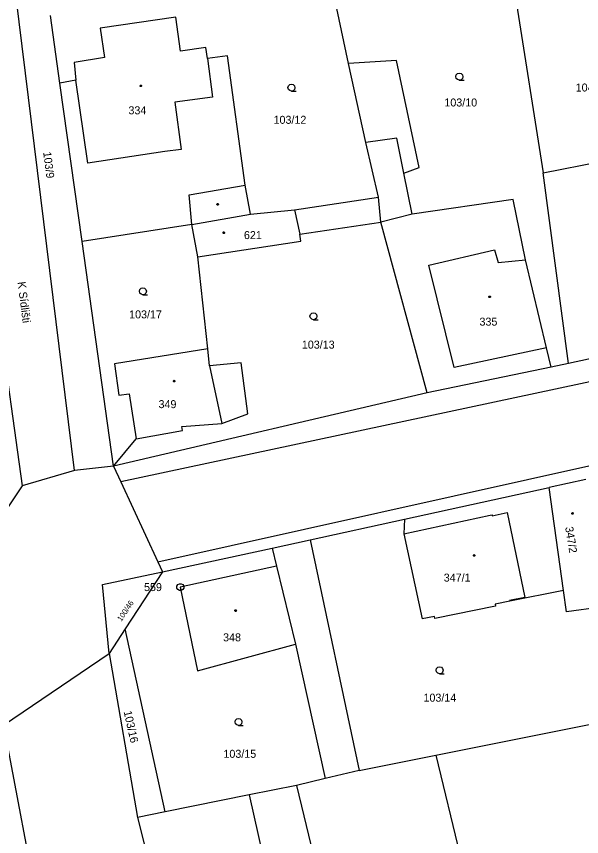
# Model space of a CAD drawing. Extents: x -757994 to -755874, y -1047691 to -1046119.
# Drawn here: x -756803.8 to -756743.8, y -1047170.3 to -1047083.2 of the extents above; entities that cross this region are included whole.
import ezdxf

# ---------------------------------------------------------------- set-up
doc = ezdxf.new("R2010")
doc.units = 0
doc.layers.add('katastrální mapa', color=7, linetype='Continuous')

msp = doc.modelspace()

# ---------------------------------------------------------------- linework, layer by layer
at = {"layer": 'katastrální mapa'}
for p, q in [((-756797.61, -1047131.45), (-756806.3, -1047061.1)), ((-756768.53, -1047088.21), (-756770.54, -1047078.93)), ((-756751.14, -1047079.14), (-756747.9, -1047099.85)), ((-756799.16, -1047090.3), (-756800.17, -1047083.12)), ((-756786.86, -1047083.32), (-756794.88, -1047084.47)), ((-756786.37, -1047086.91), (-756786.86, -1047083.32)), ((-756794.88, -1047084.47), (-756794.45, -1047087.6)), ((-756783.68, -1047086.54), (-756786.37, -1047086.91)), ((-756783.52, -1047087.68), (-756783.68, -1047086.54)), ((-756781.38, -1047087.4), (-756783.52, -1047087.68)), ((-756779.52, -1047101.14), (-756781.38, -1047087.4)), ((-756794.45, -1047087.6), (-756797.65, -1047088.11)), ((-756797.65, -1047088.11), (-756797.48, -1047090)), ((-756783.52, -1047087.68), (-756782.96, -1047091.8)), ((-756763.46, -1047087.89), (-756768.53, -1047088.21)), ((-756766.71, -1047096.61), (-756768.53, -1047088.21)), ((-756761.05, -1047099.28), (-756763.46, -1047087.89)), ((-756797.48, -1047090), (-756799.16, -1047090.3)), ((-756796.2, -1047098.8), (-756797.48, -1047090)), ((-756796.81, -1047107.13), (-756799.16, -1047090.3)), ((-756782.96, -1047091.8), (-756786.98, -1047092.34)), ((-756786.98, -1047092.34), (-756786.3, -1047097.34)), ((-756763.41, -1047096.14), (-756766.71, -1047096.61)), ((-756765.38, -1047102.41), (-756766.71, -1047096.61)), ((-756762.66, -1047099.87), (-756763.41, -1047096.14)), ((-756788.03, -1047097.58), (-756796.2, -1047098.8)), ((-756786.3, -1047097.34), (-756788.03, -1047097.58)), ((-756747.9, -1047099.85), (-756741.46, -1047098.58)), ((-756762.66, -1047099.87), (-756761.05, -1047099.28)), ((-756761.79, -1047104.23), (-756762.66, -1047099.87)), ((-756745.21, -1047120.09), (-756747.9, -1047099.85)), ((-756785.46, -1047102.16), (-756779.52, -1047101.14)), ((-756778.96, -1047104.24), (-756779.52, -1047101.14)), ((-756785.16, -1047105.31), (-756785.46, -1047102.16)), ((-756774.27, -1047103.76), (-756765.38, -1047102.41)), ((-756765.1, -1047105.06), (-756765.38, -1047102.41)), ((-756751.06, -1047102.68), (-756761.79, -1047104.23)), ((-756749.75, -1047109.07), (-756751.06, -1047102.68)), ((-756778.96, -1047104.24), (-756774.27, -1047103.76)), ((-756774.27, -1047103.76), (-756773.7, -1047106.34)), ((-756785.16, -1047105.31), (-756778.96, -1047104.24)), ((-756761.79, -1047104.23), (-756765.1, -1047105.06)), ((-756785.16, -1047105.31), (-756796.81, -1047107.13)), ((-756665.81, -1047105.58), (-756792.7, -1047132.63)), ((-756784.53, -1047108.76), (-756785.16, -1047105.31)), ((-756773.7, -1047106.34), (-756765.1, -1047105.06)), ((-756760.19, -1047123.2), (-756765.1, -1047105.06)), ((-756773.6, -1047107.1), (-756773.7, -1047106.34)), ((-756793.47, -1047130.97), (-756796.81, -1047107.13)), ((-756784.53, -1047108.76), (-756773.6, -1047107.1)), ((-756760.02, -1047109.63), (-756753.05, -1047108.02)), ((-756753.05, -1047108.02), (-756752.68, -1047109.35)), ((-756783.48, -1047118.51), (-756784.53, -1047108.76)), ((-756752.68, -1047109.35), (-756749.75, -1047109.07)), ((-756747.53, -1047118.42), (-756749.75, -1047109.07)), ((-756757.35, -1047120.51), (-756760.02, -1047109.63)), ((-756805.73, -1047114.96), (-756803.17, -1047133.07)), ((-756721.32, -1047114.93), (-756745.21, -1047120.09)), ((-756783.48, -1047118.51), (-756793.38, -1047120.12)), ((-756783.29, -1047120.32), (-756783.48, -1047118.51)), ((-756747.53, -1047118.42), (-756757.35, -1047120.51)), ((-756747.04, -1047120.47), (-756747.53, -1047118.42)), ((-756793.38, -1047120.12), (-756792.9, -1047123.46)), ((-756779.92, -1047120.01), (-756783.29, -1047120.32)), ((-756783.29, -1047120.32), (-756781.97, -1047126.44)), ((-756779.22, -1047125.43), (-756779.92, -1047120.01)), ((-756747.04, -1047120.47), (-756760.19, -1047123.2)), ((-756745.21, -1047120.09), (-756747.04, -1047120.47)), ((-756760.19, -1047123.2), (-756793.47, -1047130.97)), ((-756792.9, -1047123.46), (-756791.82, -1047123.29)), ((-756791.82, -1047123.29), (-756791.07, -1047128.07)), ((-756788.77, -1047141.15), (-756715.8, -1047124.88)), ((-756781.97, -1047126.44), (-756779.22, -1047125.43)), ((-756786.23, -1047126.76), (-756781.97, -1047126.44)), ((-756791.07, -1047128.07), (-756786.16, -1047127.21)), ((-756786.16, -1047127.21), (-756786.23, -1047126.76)), ((-756793.47, -1047130.97), (-756791.07, -1047128.07)), ((-756797.61, -1047131.45), (-756803.17, -1047133.07)), ((-756793.47, -1047130.97), (-756797.61, -1047131.45)), ((-756793.47, -1047130.97), (-756792.7, -1047132.63)), ((-756792.7, -1047132.63), (-756788.77, -1047141.15)), ((-756743.35, -1047132.39), (-756747.26, -1047133.25)), ((-756803.17, -1047133.07), (-756809.22, -1047142.06)), ((-756762.61, -1047136.62), (-756747.26, -1047133.25)), ((-756745.73, -1047144.19), (-756747.26, -1047133.25)), ((-756762.68, -1047138.17), (-756753.5, -1047136.19)), ((-756753.5, -1047136.19), (-756753.32, -1047136.15)), ((-756753.32, -1047136.15), (-756753.3, -1047136.24)), ((-756753.3, -1047136.24), (-756751.7, -1047135.89)), ((-756751.7, -1047135.89), (-756749.85, -1047144.91)), ((-756772.63, -1047138.82), (-756762.61, -1047136.62)), ((-756762.61, -1047136.62), (-756762.68, -1047138.17)), ((-756762.68, -1047138.17), (-756760.73, -1047147.19)), ((-756776.66, -1047139.69), (-756772.63, -1047138.82)), ((-756772.63, -1047138.82), (-756767.41, -1047163.3)), ((-756788.29, -1047142.19), (-756776.66, -1047139.69)), ((-756776.66, -1047139.69), (-756776.19, -1047141.6)), ((-756788.77, -1047141.15), (-756788.29, -1047142.19)), ((-756794.64, -1047143.55), (-756788.29, -1047142.19)), ((-756788.29, -1047142.19), (-756792.24, -1047148.27)), ((-756776.19, -1047141.6), (-756786.39, -1047143.82)), ((-756776.19, -1047141.6), (-756774.17, -1047149.9)), ((-756793.93, -1047150.88), (-756794.64, -1047143.55)), ((-756786.415, -1047143.82), (-756786.365, -1047143.82)), ((-756786.39, -1047143.82), (-756784.58, -1047152.7)), ((-756745.73, -1047144.19), (-756751.43, -1047145.33)), ((-756745.41, -1047146.46), (-756745.73, -1047144.19)), ((-756751.43, -1047145.33), (-756752.98, -1047145.64)), ((-756752.98, -1047145.64), (-756752.94, -1047145.86)), ((-756749.85, -1047144.91), (-756751.45, -1047145.23)), ((-756751.45, -1047145.23), (-756751.43, -1047145.33)), ((-756752.94, -1047145.86), (-756759.37, -1047147.14)), ((-756741.44, -1047145.9), (-756745.41, -1047146.46)), ((-756759.42, -1047146.93), (-756760.73, -1047147.19)), ((-756759.37, -1047147.14), (-756759.42, -1047146.93)), ((-756792.24, -1047148.27), (-756793.93, -1047150.88)), ((-756787.99, -1047167.7), (-756792.24, -1047148.27)), ((-756784.58, -1047152.7), (-756774.17, -1047149.9)), ((-756774.17, -1047149.9), (-756771.02, -1047164.16)), ((-756805.16, -1047158.5), (-756793.93, -1047150.88)), ((-756793.93, -1047150.88), (-756790.93, -1047168.29)), ((-756759.27, -1047161.67), (-756739.68, -1047157.74)), ((-756805.16, -1047158.5), (-756797.37, -1047199.42)), ((-756767.41, -1047163.3), (-756759.27, -1047161.67)), ((-756759.27, -1047161.67), (-756753.93, -1047183.96)), ((-756767.41, -1047163.3), (-756771.02, -1047164.16)), ((-756774.06, -1047164.88), (-756779.07, -1047165.89)), ((-756771.02, -1047164.16), (-756774.06, -1047164.88)), ((-756774.06, -1047164.88), (-756770.25, -1047180.54)), ((-756779.07, -1047165.89), (-756787.99, -1047167.7)), ((-756779.07, -1047165.89), (-756774.89, -1047184.86)), ((-756787.99, -1047167.7), (-756790.93, -1047168.29)), ((-756790.93, -1047168.29), (-756786.63, -1047185.42))]:
    msp.add_line(p, q, dxfattribs=at)
for points in [[(-756756.78, -1047089.99), (-756756.97, -1047089.94), (-756757.105, -1047089.805), (-756757.155, -1047089.62), (-756757.105, -1047089.435), (-756756.97, -1047089.3), (-756756.785, -1047089.25), (-756756.6, -1047089.3), (-756756.465, -1047089.435), (-756756.415, -1047089.625), (-756756.465, -1047089.815), (-756756.6, -1047089.95), (-756756.79, -1047090), (-756756.29, -1047090)], [(-756774.59, -1047091.16), (-756774.78, -1047091.11), (-756774.915, -1047090.975), (-756774.965, -1047090.79), (-756774.915, -1047090.605), (-756774.78, -1047090.47), (-756774.595, -1047090.42), (-756774.41, -1047090.47), (-756774.275, -1047090.605), (-756774.225, -1047090.795), (-756774.275, -1047090.985), (-756774.41, -1047091.12), (-756774.6, -1047091.17), (-756774.1, -1047091.17)], [(-756790.36, -1047112.78), (-756790.55, -1047112.73), (-756790.685, -1047112.595), (-756790.735, -1047112.41), (-756790.685, -1047112.225), (-756790.55, -1047112.09), (-756790.365, -1047112.04), (-756790.18, -1047112.09), (-756790.045, -1047112.225), (-756789.995, -1047112.415), (-756790.045, -1047112.605), (-756790.18, -1047112.74), (-756790.37, -1047112.79), (-756789.87, -1047112.79)], [(-756772.26, -1047115.43), (-756772.45, -1047115.38), (-756772.585, -1047115.245), (-756772.635, -1047115.06), (-756772.585, -1047114.875), (-756772.45, -1047114.74), (-756772.265, -1047114.69), (-756772.08, -1047114.74), (-756771.945, -1047114.875), (-756771.895, -1047115.065), (-756771.945, -1047115.255), (-756772.08, -1047115.39), (-756772.27, -1047115.44), (-756771.77, -1047115.44)], [(-756758.87, -1047153.02), (-756759.06, -1047152.97), (-756759.195, -1047152.835), (-756759.245, -1047152.65), (-756759.195, -1047152.465), (-756759.06, -1047152.33), (-756758.875, -1047152.28), (-756758.69, -1047152.33), (-756758.555, -1047152.465), (-756758.505, -1047152.655), (-756758.555, -1047152.845), (-756758.69, -1047152.98), (-756758.88, -1047153.03), (-756758.38, -1047153.03)], [(-756780.21, -1047158.51), (-756780.4, -1047158.46), (-756780.535, -1047158.325), (-756780.585, -1047158.14), (-756780.535, -1047157.955), (-756780.4, -1047157.82), (-756780.215, -1047157.77), (-756780.03, -1047157.82), (-756779.895, -1047157.955), (-756779.845, -1047158.145), (-756779.895, -1047158.335), (-756780.03, -1047158.47), (-756780.22, -1047158.52), (-756779.72, -1047158.52)]]:
    msp.add_lwpolyline(points, dxfattribs=at)
for points in [[(-756790.59, -1047090.515), (-756790.54, -1047090.525), (-756790.515, -1047090.57), (-756790.505, -1047090.6), (-756790.515, -1047090.645), (-756790.555, -1047090.68), (-756790.59, -1047090.685), (-756790.635, -1047090.67), (-756790.665, -1047090.64), (-756790.675, -1047090.6), (-756790.665, -1047090.555), (-756790.625, -1047090.52)], [(-756782.385, -1047103.105), (-756782.34, -1047103.18), (-756782.385, -1047103.255), (-756782.475, -1047103.255), (-756782.52, -1047103.18), (-756782.475, -1047103.105)], [(-756781.78, -1047106.105), (-756781.73, -1047106.115), (-756781.705, -1047106.16), (-756781.695, -1047106.19), (-756781.705, -1047106.235), (-756781.745, -1047106.27), (-756781.78, -1047106.275), (-756781.825, -1047106.26), (-756781.855, -1047106.23), (-756781.865, -1047106.19), (-756781.855, -1047106.145), (-756781.815, -1047106.11)], [(-756753.57, -1047112.915), (-756753.52, -1047112.925), (-756753.495, -1047112.97), (-756753.485, -1047113), (-756753.495, -1047113.045), (-756753.535, -1047113.08), (-756753.57, -1047113.085), (-756753.615, -1047113.07), (-756753.645, -1047113.04), (-756753.655, -1047113), (-756753.645, -1047112.955), (-756753.605, -1047112.92)], [(-756787.04, -1047121.865), (-756786.99, -1047121.875), (-756786.965, -1047121.92), (-756786.955, -1047121.95), (-756786.965, -1047121.995), (-756787.005, -1047122.03), (-756787.04, -1047122.035), (-756787.085, -1047122.02), (-756787.115, -1047121.99), (-756787.125, -1047121.95), (-756787.115, -1047121.905), (-756787.075, -1047121.87)], [(-756744.77, -1047135.915), (-756744.72, -1047135.925), (-756744.695, -1047135.97), (-756744.685, -1047136), (-756744.695, -1047136.045), (-756744.735, -1047136.08), (-756744.77, -1047136.085), (-756744.815, -1047136.07), (-756744.845, -1047136.04), (-756744.855, -1047136), (-756744.845, -1047135.955), (-756744.805, -1047135.92)], [(-756755.21, -1047140.375), (-756755.16, -1047140.385), (-756755.135, -1047140.43), (-756755.125, -1047140.46), (-756755.135, -1047140.505), (-756755.175, -1047140.54), (-756755.21, -1047140.545), (-756755.255, -1047140.53), (-756755.285, -1047140.5), (-756755.295, -1047140.46), (-756755.285, -1047140.415), (-756755.245, -1047140.38)], [(-756786.295, -1047143.46), (-756786.125, -1047143.555), (-756786.03, -1047143.725), (-756786.03, -1047143.92), (-756786.125, -1047144.09), (-756786.295, -1047144.185), (-756786.49, -1047144.185), (-756786.66, -1047144.09), (-756786.755, -1047143.92), (-756786.755, -1047143.725), (-756786.66, -1047143.555), (-756786.49, -1047143.46)], [(-756780.53, -1047146.235), (-756780.48, -1047146.245), (-756780.455, -1047146.29), (-756780.445, -1047146.32), (-756780.455, -1047146.365), (-756780.495, -1047146.4), (-756780.53, -1047146.405), (-756780.575, -1047146.39), (-756780.605, -1047146.36), (-756780.615, -1047146.32), (-756780.605, -1047146.275), (-756780.565, -1047146.24)]]:
    msp.add_lwpolyline(points, close=True, dxfattribs=at)

# ---------------------------------------------------------------- texts
for s, p in [('104/20', (-756744.441, -1047091.2)), ('103/10', (-756758.373, -1047092.79)), ('334', (-756791.894, -1047093.62)), ('103/12', (-756776.497, -1047094.63)), ('621', (-756779.64, -1047106.87)), ('103/17', (-756791.82, -1047115.29)), ('335', (-756754.648, -1047116.06)), ('103/13', (-756773.494, -1047118.5)), ('349', (-756788.701, -1047124.82)), ('347/1', (-756758.441, -1047143.24)), ('559', (-756790.237, -1047144.245)), ('348', (-756781.851, -1047149.58)), ('103/14', (-756760.59, -1047155.99)), ('103/15', (-756781.814, -1047161.95))]:
    msp.add_text(s, height=0.85, dxfattribs=at).set_placement(p)
for s, height, rotation, p in [('103/9', 0.85, 277.31157, (-756800.944, -1047097.644)), ('K Sídlišti', 0.85, 277.19698, (-756803.658, -1047111.439)), ('347/2', 0.85, 279.31693, (-756745.561, -1047137.467)), ('100/46', 0.595, 56.20716, (-756792.644, -1047147.516)), ('103/16', 0.85, 282.52549, (-756792.404, -1047157.042))]:
    msp.add_text(s, height=height, rotation=rotation, dxfattribs=at).set_placement(p)

doc.saveas('drawing.dxf')
